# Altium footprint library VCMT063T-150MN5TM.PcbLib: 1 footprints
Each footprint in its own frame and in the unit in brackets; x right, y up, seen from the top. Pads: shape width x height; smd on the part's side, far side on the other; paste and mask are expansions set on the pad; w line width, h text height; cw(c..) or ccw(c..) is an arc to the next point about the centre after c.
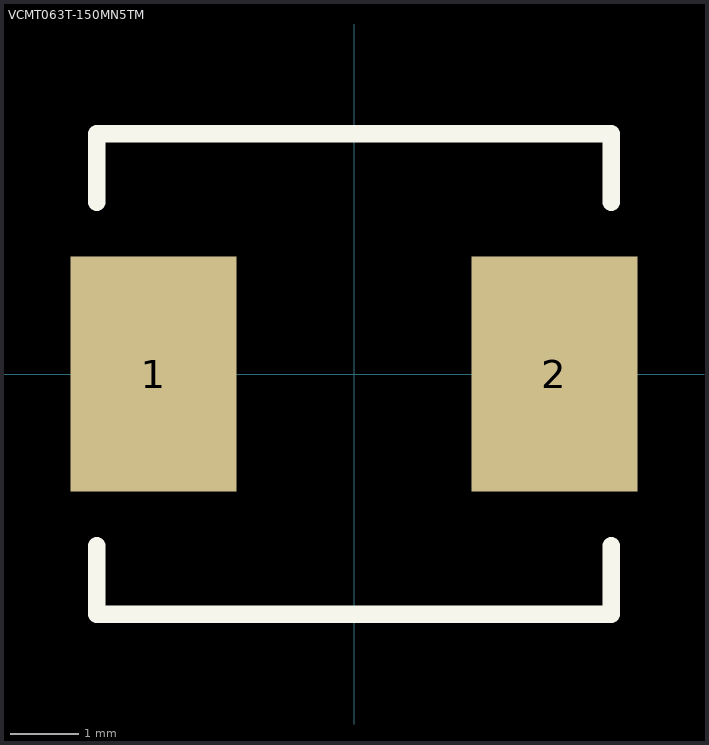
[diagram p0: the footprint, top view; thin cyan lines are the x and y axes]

## VCMT063T-150MN5TM [mil]
height 118.11
pads (2):
  rect 95x135 smd: 1(-115,0) 2(115,0)
Top Overlay:
  lines w10: -147.64,-98.43 -147.64,-137.8 147.64,-137.8 147.64,-98.43 ; -147.64,98.43 -147.64,137.8 147.64,137.8 147.64,98.43
M5 Assembly Top:
  text ".Designator" at -70.87,-20.22 h40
